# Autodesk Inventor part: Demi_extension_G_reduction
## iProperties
Shininess: 64.0
Length Units: 11269
Angle Units: 11279
Time Units: 11290
Mass Units: 11283
Length Display Precision: 3
Angle Display Precision: 2
Compacted: True
Part Number: Demi_extension_G_reduction
Document SubType Name: Modeling
Created: 2008-02
Material: Acier inoxydable, austénitique
Designer: Pascal
Density: 0.0
Volumn: 0.0
Area: 0.0
PropertySet Name: Model Information
Control State: 0
Master: False
Checked Out: False
MATIERE_PIECE: X2CrNi 18-11
OBSERVATIONS: Tôle ep. 15/10
DESIGNATION: Demi-extension gauche
Author: Pascal
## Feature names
1. Extrusion1
2. Extrusion2
3. Extrusion3
